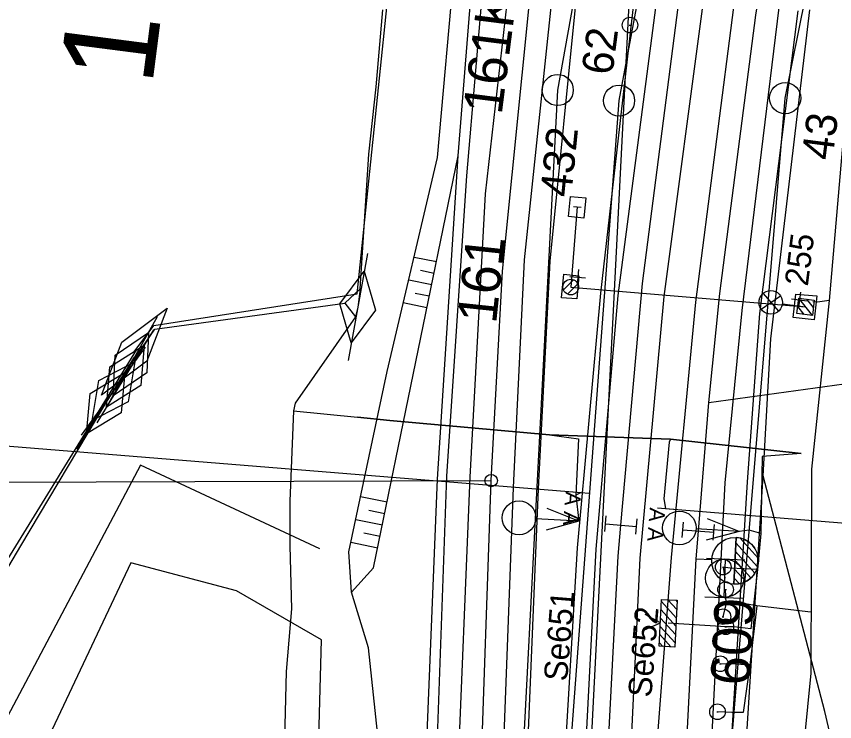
# Model space of a CAD drawing. Extents: x -598638 to -597933, y -1164002 to -1161904.
# Drawn here: x -598282.7 to -598230.2, y -1163124 to -1163078.8 of the extents above; entities that cross this region are included whole.
import ezdxf

# ---------------------------------------------------------------- set-up
doc = ezdxf.new("R2010")
doc.units = 0
for name, color, linetype in [('Vrstva 1', 7, 'Continuous'), ('Vrstva 11', 7, 'Continuous'), ('Vrstva 12', 7, 'Continuous'), ('Vrstva 2', 7, 'Continuous'), ('Vrstva 25', 7, 'Continuous'), ('Vrstva 26', 7, 'Continuous'), ('Vrstva 28', 7, 'Continuous'), ('Vrstva 3', 7, 'Continuous'), ('Vrstva 35', 7, 'Continuous'), ('Vrstva 36', 7, 'Continuous'), ('Vrstva 4', 7, 'Continuous'), ('Vrstva 43', 7, 'Continuous'), ('Vrstva 44', 7, 'Continuous'), ('Vrstva 48', 7, 'Continuous'), ('Vrstva 49', 7, 'Continuous'), ('Vrstva 51', 7, 'Continuous'), ('Vrstva 6', 7, 'Continuous'), ('Vrstva 63', 7, 'Continuous'), ('Vrstva 7', 7, 'Continuous')]:
    doc.layers.add(name, color=color, linetype=linetype)

msp = doc.modelspace()

# ---------------------------------------------------------------- linework, layer by layer
at = {"layer": 'Vrstva 1'}
for p, q in [((-598238.259, -1163103.539), (-598111.953, -1163086.041)), ((-598328.722, -1163108.807), (-598252.219, -1163108.544))]:
    msp.add_line(p, q, dxfattribs=at)
for points in [[(-598245.185, -1163146.686), (-598244.89, -1163128.996), (-598244.069, -1163113.383), (-598243.892, -1163111.402), (-598242.508, -1163095.903), (-598240.221, -1163078.173), (-598237.7, -1163063), (-598234.456, -1163047.036), (-598230.819, -1163031.867), (-598224.044, -1163008.196), (-598218.147, -1162990.962), (-598212.612, -1162976.381), (-598210.162, -1162970.38), (-598207.127, -1162963.269), (-598201.66, -1162951.286), (-598200.923, -1162949.67), (-598193.375, -1162934.568), (-598185.535, -1162920.228)], [(-598240.169, -1163146.755), (-598239.921, -1163130.309), (-598239.07, -1163113.566), (-598238.926, -1163111.785), (-598238.259, -1163103.539), (-598237.54, -1163096.536), (-598235.247, -1163078.679), (-598233.075, -1163065.413), (-598229.628, -1163048.216), (-598226.08, -1163033.339), (-598219.335, -1163009.739), (-598213.514, -1162992.625), (-598208.094, -1162978.373), (-598205.572, -1162972.188), (-598202.745, -1162965.549), (-598196.38, -1162951.607), (-598188.854, -1162936.558), (-598181.238, -1162922.581)], [(-598252.219, -1163108.544), (-598251.499, -1163095.121), (-598249.615, -1163076.345), (-598247.361, -1163061.217), (-598244.383, -1163046.003), (-598242.664, -1163039.018), (-598240.128, -1163028.714), (-598235.674, -1163014.439), (-598232.556, -1163004.447), (-598225.931, -1162987.141), (-598216.898, -1162967.125), (-598213.283, -1162959.931), (-598210.092, -1162954.031), (-598206.72, -1162947.797)], [(-598254.941, -1163186.204), (-598253.423, -1163142.963), (-598252.923, -1163128.846), (-598252.219, -1163108.544)]]:
    msp.add_lwpolyline(points, dxfattribs=at)
msp.add_circle((-598252.219, -1163108.544), 0.4, dxfattribs=at)
at = {"layer": 'Vrstva 11'}
for p, q in [((-598247.571, -1163096.314), (-598246.925, -1163095.668)), ((-598247.311, -1163096.584), (-598246.656, -1163095.929)), ((-598231.616, -1163097.956), (-598232.487, -1163096.847)), ((-598231.55, -1163097.433), (-598231.964, -1163096.907)), ((-598232.142, -1163097.893), (-598232.55, -1163097.373))]:
    msp.add_line(p, q, dxfattribs=at)
for points in [[(-598247.11, -1163096.13), (-598232.05, -1163097.4)], [(-598232.606, -1163097.837), (-598232.487, -1163096.844), (-598231.494, -1163096.963), (-598231.613, -1163097.956), (-598232.606, -1163097.837)]]:
    msp.add_lwpolyline(points, dxfattribs=at)
msp.add_lwpolyline([(-598232.606, -1163097.837), (-598232.487, -1163096.844), (-598231.494, -1163096.963), (-598231.613, -1163097.956)], close=True, dxfattribs=at)
msp.add_circle((-598247.11, -1163096.13), 0.5, dxfattribs=at)
at = {"layer": 'Vrstva 12'}
for points in [[(-598246.15, -1163090.4), (-598246.28, -1163091.71), (-598247.26, -1163091.61), (-598247.13, -1163090.33), (-598246.15, -1163090.4)], [(-598246.6, -1163095.4), (-598246.72, -1163096.89), (-598247.71, -1163096.82), (-598247.55, -1163095.31), (-598246.6, -1163095.4)], [(-598232.85, -1163098.08), (-598232.67, -1163096.58), (-598231.32, -1163096.7), (-598231.5, -1163098.23), (-598232.85, -1163098.08)]]:
    msp.add_lwpolyline(points, dxfattribs=at)
at = {"layer": 'Vrstva 2'}
for p, q in [((-598236.497, -1163112.195), (-598236.649, -1163115.191)), ((-598236.649, -1163115.191), (-598236.497, -1163112.195)), ((-598235.126, -1163114.074), (-598236.514, -1163112.537)), ((-598235.085, -1163113.523), (-598236.252, -1163112.231)), ((-598235.299, -1163114.479), (-598236.543, -1163113.102)), ((-598239.07, -1163113.566), (-598238.071, -1163113.617)), ((-598235.557, -1163114.791), (-598236.572, -1163113.667)), ((-598235.887, -1163115.022), (-598236.601, -1163114.232)), ((-598236.299, -1163115.164), (-598236.629, -1163114.796))]:
    msp.add_line(p, q, dxfattribs=at)
msp.add_lwpolyline([(-598240.169, -1163146.755), (-598239.921, -1163130.309), (-598239.07, -1163113.566)], dxfattribs=at)
msp.add_circle((-598236.573, -1163113.693), 1.5, dxfattribs=at)
msp.add_arc((-598236.573, -1163113.693), 1.5, 267.0903, 87.0903, dxfattribs=at)
at = {"layer": 'Vrstva 25'}
for p, q in [((-598234.909, -1163097.538), (-598233.666, -1163096.685)), ((-598234.766, -1163096.533), (-598233.795, -1163097.687)), ((-598233.538, -1163097.212), (-598232.05, -1163097.4)), ((-598237.38, -1163114.09), (-598237.28, -1163114.09)), ((-598237.233, -1163115.538), (-598237.133, -1163115.538)), ((-598237.402, -1163117.276), (-598237.302, -1163117.276)), ((-598237.22, -1163117.92), (-598237.12, -1163117.92)), ((-598237.57, -1163120.295), (-598237.47, -1163120.295)), ((-598237.75, -1163123.375), (-598237.65, -1163123.375))]:
    msp.add_line(p, q, dxfattribs=at)
for centre, radius in [((-598234.283, -1163097.113), 0.754), ((-598237.329, -1163114.09), 0.5), ((-598237.183, -1163115.538), 0.5), ((-598237.352, -1163117.276), 0.5), ((-598237.164, -1163117.92), 0.5), ((-598237.52, -1163120.295), 0.5), ((-598237.7, -1163123.375), 0.5)]:
    msp.add_circle(centre, radius, dxfattribs=at)
at = {"layer": 'Vrstva 26'}
for points in [[(-598211.382, -1162940.065), (-598193.601, -1162950.161), (-598191.584, -1162951.092), (-598198.026, -1162967.205), (-598208.688, -1162993.504), (-598209.03, -1162994.474), (-598214.707, -1163009.33), (-598218.558, -1163024.082), (-598220.34, -1163031.684), (-598220.756, -1163034.417), (-598224.218, -1163049.876), (-598227.646, -1163065.71), (-598228.067, -1163068.213), (-598230.531, -1163097), (-598231.676, -1163107.807), (-598231.723, -1163120.907), (-598232.574, -1163129.537), (-598231.426, -1163150.759)], [(-598275.109, -1163100.278), (-598273.844, -1163098.6), (-598260.82, -1163096.56), (-598257.46, -1163064.133), (-598260.892, -1163061.98), (-598261.588, -1163060.825), (-598273.046, -1163054.115), (-598278.317, -1163050.938), (-598277.838, -1163049.549), (-598266.333, -1163029.926), (-598256.715, -1163013.724), (-598243.958, -1162995.4), (-598237.708, -1162985.218), (-598234.448, -1162986.452), (-598224.79, -1162970.405), (-598223.9, -1162969.714), (-598230.146, -1162966.324)], [(-598230.531, -1163097), (-598231.278, -1163097.099), (-598231.586, -1163097.079)], [(-598277.216, -1163103.073), (-598275.908, -1163099.676), (-598273.002, -1163097.483), (-598274.31, -1163100.88), (-598277.216, -1163103.073)], [(-598329.728, -1163196.743), (-598319.392, -1163178.856), (-598305.552, -1163153.711), (-598290.936, -1163126.707), (-598284.955, -1163116.365), (-598274.949, -1163100.139)], [(-598231.709, -1163116.985), (-598235.178, -1163116.569), (-598236.052, -1163116.428), (-598237.149, -1163116.405), (-598237.183, -1163115.538)], [(-598235.178, -1163116.569), (-598235.634, -1163120.375), (-598236.055, -1163123.43), (-598236.789, -1163123.42), (-598237.7, -1163123.375)], [(-598237.149, -1163116.405), (-598237.352, -1163117.276)], [(-598235.634, -1163120.375), (-598236.512, -1163120.331), (-598237.52, -1163120.295)]]:
    msp.add_lwpolyline(points, dxfattribs=at)
at = {"layer": 'Vrstva 28'}
for p, q in [((-598260.148, -1163093.975), (-598261.393, -1163100.845)), ((-598261.916, -1163097.203), (-598260.355, -1163095.121)), ((-598260.355, -1163095.121), (-598259.625, -1163097.618)), ((-598261.186, -1163099.7), (-598261.916, -1163097.203)), ((-598259.625, -1163097.618), (-598261.186, -1163099.7)), ((-598277.026, -1163104.116), (-598273.614, -1163098.024)), ((-598277.482, -1163104.834), (-598273.858, -1163098.866)), ((-598276.336, -1163100.502), (-598274.183, -1163099.04)), ((-598274.183, -1163099.04), (-598274.304, -1163101.639)), ((-598278.48, -1163105.636), (-598274.381, -1163099.984)), ((-598276.665, -1163101.246), (-598274.463, -1163099.861)), ((-598274.463, -1163099.861), (-598274.675, -1163102.454)), ((-598278.796, -1163106.537), (-598275.085, -1163100.624)), ((-598276.457, -1163103.101), (-598276.336, -1163100.502)), ((-598277.373, -1163102.127), (-598275.064, -1163100.926)), ((-598275.064, -1163100.926), (-598275.488, -1163103.493)), ((-598277.926, -1163102.962), (-598275.703, -1163101.609)), ((-598276.878, -1163103.839), (-598276.665, -1163101.246)), ((-598274.304, -1163101.639), (-598276.457, -1163103.101)), ((-598275.703, -1163101.609), (-598275.954, -1163104.199)), ((-598277.796, -1163104.694), (-598277.373, -1163102.127)), ((-598274.675, -1163102.454), (-598276.878, -1163103.839)), ((-598278.177, -1163105.551), (-598277.926, -1163102.962)), ((-598275.488, -1163103.493), (-598277.796, -1163104.694)), ((-598275.954, -1163104.199), (-598278.177, -1163105.551)), ((-598240.343, -1163117.354), (-598241.294, -1163116.308)), ((-598240.318, -1163116.825), (-598240.888, -1163116.197)), ((-598240.292, -1163116.296), (-598240.358, -1163116.222)), ((-598240.369, -1163117.885), (-598241.319, -1163116.838)), ((-598240.394, -1163118.414), (-598241.345, -1163117.367)), ((-598240.42, -1163118.943), (-598241.371, -1163117.897)), ((-598240.685, -1163119.21), (-598241.396, -1163118.427)), ((-598241.214, -1163119.184), (-598241.422, -1163118.956))]:
    msp.add_line(p, q, dxfattribs=at)
for points in [[(-598260.62, -1163096.25), (-598260.07, -1163087.61), (-598259.59, -1163083.29), (-598259.16, -1163078.34)], [(-598261.6, -1163097.17), (-598260.62, -1163096.25), (-598260.77, -1163097.41), (-598260.92, -1163098.05)], [(-598311.69, -1163165.97), (-598300.22, -1163144.81), (-598288.63, -1163123.27), (-598282.38, -1163112.74), (-598276.94, -1163103.58), (-598276.43, -1163102.81), (-598275.67, -1163101.85), (-598275.32, -1163101.07), (-598273.79, -1163098.83), (-598261.6, -1163097.17), (-598260.92, -1163098.05), (-598264.78, -1163103.58), (-598264.9, -1163104.07), (-598265.13, -1163109.86), (-598265.13, -1163112.72), (-598265.03, -1163116.78), (-598265.37, -1163120.79), (-598265.62, -1163131.18), (-598265.34, -1163148.04), (-598265.46, -1163176.63)], [(-598264.9, -1163104.07), (-598260.79, -1163104.47), (-598258.71, -1163104.69), (-598248.47, -1163105.62), (-598240.71, -1163105.88), (-598232.34, -1163106.8), (-598234.84, -1163106.99), (-598234.93, -1163111.94), (-598235.14, -1163114.25), (-598235.56, -1163118.05), (-598236.65, -1163117.92), (-598237.17, -1163117.92), (-598240.86, -1163117.7)], [(-598248.47, -1163105.62), (-598246.62, -1163105.87), (-598246.78, -1163109.47), (-598246.59, -1163111.14)], [(-598240.71, -1163105.88), (-598240.79, -1163106.09), (-598241.15, -1163109.72), (-598241.04, -1163110.34)], [(-598246.44, -1163109.31), (-598246.78, -1163109.47)], [(-598234.93, -1163111.94), (-598235.67, -1163111.73), (-598236.31, -1163111.81)], [(-598235.14, -1163114.25), (-598236.88, -1163114.17), (-598237.33, -1163114.09), (-598237.23, -1163114.81)], [(-598241.433, -1163119.173), (-598241.287, -1163116.178), (-598240.288, -1163116.226), (-598240.433, -1163119.222), (-598241.433, -1163119.173)], [(-598242.382, -1163118.127), (-598241.359, -1163117.676), (-598242.334, -1163117.127)]]:
    msp.add_lwpolyline(points, dxfattribs=at)
msp.add_lwpolyline([(-598241.433, -1163119.173), (-598241.287, -1163116.178), (-598240.288, -1163116.226), (-598240.433, -1163119.222)], close=True, dxfattribs=at)
at = {"layer": 'Vrstva 3'}
for p, q in [((-598246.59, -1163111.14), (-598248.62, -1163110.341)), ((-598246.59, -1163111.14), (-598249.346, -1163110.993)), ((-598244.934, -1163111.808), (-598244.842, -1163110.812)), ((-598242.942, -1163111.992), (-598242.85, -1163110.996)), ((-598236.31, -1163111.81), (-598238.336, -1163110.999)), ((-598246.59, -1163111.14), (-598248.694, -1163111.719)), ((-598244.888, -1163111.31), (-598242.896, -1163111.494)), ((-598239.962, -1163112.204), (-598239.883, -1163111.207)), ((-598236.31, -1163111.81), (-598239.065, -1163111.647)), ((-598237.969, -1163112.363), (-598237.89, -1163111.366)), ((-598239.923, -1163111.706), (-598237.929, -1163111.864)), ((-598236.31, -1163111.81), (-598238.417, -1163112.377)), ((-598238.412, -1163113.53), (-598235.95, -1163113.628)), ((-598237.279, -1163116.041), (-598237.181, -1163113.579)), ((-598238.51, -1163115.992), (-598236.048, -1163116.09))]:
    msp.add_line(p, q, dxfattribs=at)
for centre, radius in [((-598250.428, -1163110.932), 1.084), ((-598240.146, -1163111.586), 1.084), ((-598237.234, -1163114.804), 1.232)]:
    msp.add_circle(centre, radius, dxfattribs=at)
at = {"layer": 'Vrstva 35'}
msp.add_lwpolyline([(-598232.34, -1163106.8), (-598240.71, -1163105.88), (-598248.47, -1163105.62), (-598258.71, -1163104.69), (-598260.79, -1163104.47)], dxfattribs=at)
at = {"layer": 'Vrstva 36'}
msp.add_line((-598246.942, -1163090.965), (-598246.444, -1163091.014), dxfattribs=at)
msp.add_lwpolyline([(-598246.69, -1163090.99), (-598247.11, -1163096.13)], dxfattribs=at)
at = {"layer": 'Vrstva 4'}
for points in [[(-598398.167, -1163553.239), (-598376.487, -1163515.918), (-598348.795, -1163467.979), (-598339.716, -1163452.202), (-598323.266, -1163423.236), (-598308.372, -1163396.471), (-598302.715, -1163384.123), (-598298.324, -1163372.137), (-598289.593, -1163344.221), (-598282.967, -1163321.229), (-598274.797, -1163290.285), (-598269.404, -1163272.781), (-598266.519, -1163258.633), (-598263.896, -1163241.651), (-598261.185, -1163218.05), (-598260.503, -1163217.001), (-598259.092, -1163201.513), (-598258.163, -1163186.176), (-598256.557, -1163141.317), (-598256.485, -1163129.008), (-598255.651, -1163108.451), (-598254.34, -1163087.718), (-598253.319, -1163075.132)], [(-598321.684, -1163563.952), (-598314.649, -1163552.341), (-598302.065, -1163529.781), (-598292.77, -1163512.02), (-598281.731, -1163489.572), (-598274.163, -1163472.668), (-598266.066, -1163452.17), (-598258.953, -1163431.709), (-598252.674, -1163410.241), (-598246.46, -1163386.104), (-598243.144, -1163368.884), (-598239.955, -1163345.756), (-598237.56, -1163323.253), (-598236.679, -1163305.47), (-598236.283, -1163282.744), (-598236.431, -1163244.569), (-598236.596, -1163214.625), (-598236.873, -1163174.881), (-598236.229, -1163131.239), (-598234.781, -1163108.249), (-598234.285, -1163099.455), (-598231.787, -1163078.342)], [(-598283.36, -1163489.15), (-598275.736, -1163471.917), (-598267.551, -1163451.028), (-598260.793, -1163431.262), (-598254.345, -1163409.722), (-598248.47, -1163385.636), (-598245.045, -1163368.352), (-598241.712, -1163345.6), (-598239.462, -1163322.753), (-598238.478, -1163305.467), (-598238.203, -1163283.28), (-598238.406, -1163245.16), (-598238.376, -1163215.168), (-598238.53, -1163175.26), (-598238.394, -1163131.328), (-598237.202, -1163108.683), (-598236.122, -1163097.625), (-598233.737, -1163078.205)]]:
    msp.add_lwpolyline(points, dxfattribs=at)
at = {"layer": 'Vrstva 43'}
for centre in [(-598247.948, -1163083.491), (-598244.014, -1163084.171), (-598233.358, -1163084.011)]:
    msp.add_circle(centre, 1, dxfattribs=at)
at = {"layer": 'Vrstva 44'}
for points in [[(-598295.758, -1163493.483), (-598278.118, -1163452.874), (-598264.209, -1163410.565), (-598254.468, -1163367.19), (-598248.62, -1163321.577), (-598253.497, -1163320.887), (-598249.615, -1163272.581), (-598247.635, -1163222.481), (-598247.486, -1163176.779), (-598247.442, -1163130.148), (-598244.014, -1163084.171), (-598235.33, -1163037.762), (-598224.817, -1163002.559), (-598219.379, -1163002.169), (-598206.652, -1162968.487), (-598191.401, -1162936.053), (-598173.754, -1162904.506), (-598155.689, -1162873.083), (-598136.14, -1162838.446), (-598116.776, -1162804.197)], [(-598286.823, -1163498.793), (-598268.977, -1163457.491), (-598254.684, -1163414.899), (-598244.494, -1163370.7), (-598238.629, -1163323.594), (-598237.183, -1163277.386), (-598237.387, -1163227.403), (-598237.546, -1163176.839), (-598237.218, -1163130.355), (-598233.358, -1163084.011), (-598224.142, -1163038.365), (-598215.269, -1163005.578), (-598224.817, -1163002.559)], [(-598280.199, -1163332.648), (-598271.397, -1163301.809), (-598265.446, -1163302.712), (-598259.208, -1163252.741), (-598251.788, -1163176.385), (-598250.383, -1163130.296), (-598247.948, -1163083.491), (-598241.007, -1163044.927)]]:
    msp.add_lwpolyline(points, dxfattribs=at)
at = {"layer": 'Vrstva 48'}
for p, q in [((-598257.161, -1163094.203), (-598255.73, -1163094.497)), ((-598256.752, -1163095.053), (-598255.88, -1163095.231)), ((-598257.506, -1163095.664), (-598256.031, -1163095.966)), ((-598257.08, -1163096.517), (-598256.182, -1163096.701)), ((-598257.851, -1163097.124), (-598256.332, -1163097.435)), ((-598260.595, -1163109.564), (-598258.89, -1163109.914)), ((-598260.067, -1163110.438), (-598259.041, -1163110.649)), ((-598260.906, -1163111.032), (-598259.192, -1163111.383)), ((-598260.374, -1163111.906), (-598259.342, -1163112.118)), ((-598261.217, -1163112.499), (-598259.493, -1163112.853))]:
    msp.add_line(p, q, dxfattribs=at)
at = {"layer": 'Vrstva 49'}
for points in [[(-598299.445, -1163361.058), (-598297.068, -1163359.059), (-598293.068, -1163343.621), (-598287.79, -1163320.649), (-598279.637, -1163288.312), (-598274.636, -1163271.434), (-598271.523, -1163257.595), (-598269.283, -1163241.904), (-598267.104, -1163218.072), (-598264.127, -1163206.783), (-598263.144, -1163204.971), (-598260.62, -1163202.843), (-598259.578, -1163186.018), (-598258.253, -1163141.176), (-598259.192, -1163127.718), (-598260.075, -1163119.279), (-598261.182, -1163115.692), (-598261.349, -1163113.122), (-598258.894, -1163101.538), (-598255.65, -1163087.809), (-598254.518, -1163075.132), (-598252.098, -1163061.479), (-598247.841, -1163044.835)], [(-598261.182, -1163115.692), (-598259.756, -1163114.136), (-598254.34, -1163087.718)], [(-598263.212, -1163112.925), (-598274.704, -1163107.546), (-598303.252, -1163161.452), (-598319.987, -1163201.454), (-598331.61, -1163221.279), (-598337.803, -1163227.955), (-598369.667, -1163281.996), (-598397.721, -1163336.904), (-598402.66, -1163348.84), (-598400.565, -1163353.737), (-598397.481, -1163355.879), (-598399.949, -1163362.495), (-598406.763, -1163364.325), (-598409.804, -1163366.381), (-598423.526, -1163399.322), (-598428.665, -1163409.066), (-598433.221, -1163423.229), (-598435.507, -1163449.626)], [(-598218.985, -1163327.148), (-598212.65, -1163283.715), (-598208.558, -1163248.195), (-598210.74, -1163214.935), (-598218.187, -1163174.338), (-598225.543, -1163145.969), (-598230.824, -1163123.355), (-598234.781, -1163108.249)], [(-598271.914, -1163217.222), (-598269.776, -1163209.288), (-598269.073, -1163206.337), (-598265.809, -1163203.939), (-598262.679, -1163201.583), (-598261.749, -1163188.913), (-598261.649, -1163166.383), (-598262.017, -1163142.76), (-598263.36, -1163128.202), (-598263.105, -1163118.751), (-598268.545, -1163115.616), (-598275.334, -1163113.816), (-598312.096, -1163191.704), (-598312.746, -1163196.691)]]:
    msp.add_lwpolyline(points, dxfattribs=at)
at = {"layer": 'Vrstva 51'}
for points in [[(-598243.76, -1163139.382), (-598243.393, -1163128.836), (-598242.662, -1163113.52), (-598241.121, -1163096.732), (-598238.542, -1163077.297), (-598236.364, -1163063.881), (-598233.006, -1163047.35), (-598229.452, -1163032.186), (-598222.566, -1163008.635), (-598216.788, -1162991.447), (-598211.314, -1162977.141), (-598198.954, -1162949.031), (-598191.954, -1162935.136), (-598181.215, -1162915.654), (-598172.367, -1162900.092), (-598146.639, -1162854.694), (-598125.435, -1162817.431), (-598123.403, -1162813.873), (-598093.874, -1162762.323), (-598071.494, -1162722.83), (-598058.726, -1162701.732), (-598043.403, -1162678.606), (-598026.165, -1162652.845)], [(-598397.431, -1163553.318), (-598375.745, -1163515.943), (-598348.098, -1163468.333), (-598322.38, -1163423.533), (-598307.542, -1163396.818), (-598301.86, -1163384.541), (-598297.285, -1163372.341), (-598293.283, -1163359.379), (-598288.845, -1163344.448), (-598282.25, -1163321.235), (-598273.825, -1163290.423), (-598265.756, -1163258.778), (-598260.545, -1163219.203), (-598259.744, -1163217.171), (-598258.57, -1163201.891), (-598257.659, -1163186.255), (-598256.038, -1163142.193), (-598255.793, -1163128.623), (-598255.065, -1163108.27), (-598253.781, -1163088.998), (-598252.62, -1163075.466)], [(-598396.078, -1163554.151), (-598374.443, -1163516.599), (-598347.031, -1163469.014), (-598321.218, -1163424.261), (-598306.253, -1163397.723), (-598300.608, -1163385.153), (-598295.814, -1163372.93), (-598291.849, -1163359.988), (-598287.46, -1163344.41), (-598281.154, -1163322.32), (-598272.412, -1163291.197), (-598264.229, -1163259.135), (-598258.972, -1163219.27), (-598257.327, -1163201.644), (-598256.369, -1163186.491), (-598254.79, -1163142.649), (-598254.397, -1163128.629), (-598253.571, -1163108.317), (-598252.585, -1163090.153), (-598250.983, -1163076.012)], [(-598384.985, -1163560.822), (-598363.176, -1163523.063), (-598335.955, -1163475.581), (-598310.179, -1163431.066), (-598295.149, -1163404.135), (-598288.465, -1163389.583), (-598283.96, -1163377.815), (-598279.772, -1163364.473), (-598275.196, -1163348.33), (-598271.933, -1163336.198), (-598269.31, -1163324.265), (-598265.084, -1163292.029), (-598261.053, -1163259.678), (-598256.104, -1163220.296), (-598254.426, -1163201.671), (-598253.667, -1163187.936), (-598252.018, -1163143.494), (-598251.534, -1163128.863), (-598250.791, -1163108.998), (-598250.069, -1163094.383), (-598248.218, -1163076.729)], [(-598305.922, -1163504.285), (-598297.335, -1163487.137), (-598287.92, -1163465.981), (-598279.035, -1163443.103), (-598273.208, -1163425.978), (-598267.2, -1163406.108), (-598261.011, -1163380.887), (-598258.166, -1163366.304), (-598254.569, -1163343.143), (-598252.435, -1163322.084), (-598250.965, -1163305.051), (-598249.488, -1163286.133), (-598247.962, -1163266.793), (-598246.718, -1163245.404), (-598246.637, -1163214.417), (-598246.633, -1163173.748), (-598246.347, -1163129.422), (-598245.484, -1163112.939), (-598244.076, -1163096.672), (-598241.475, -1163076.865)], [(-598298.888, -1163486.593), (-598289.113, -1163465.583), (-598279.905, -1163442.964), (-598274.107, -1163425.699), (-598268.268, -1163405.757), (-598262.238, -1163380.596), (-598259.701, -1163366.461), (-598255.999, -1163342.847), (-598253.859, -1163322.319), (-598252.407, -1163304.609), (-598250.982, -1163286.31), (-598249.458, -1163266.6), (-598248.128, -1163245.447), (-598247.963, -1163214.31), (-598248.01, -1163173.778), (-598247.475, -1163130.652), (-598247.596, -1163128.349), (-598246.685, -1163112.866), (-598245.177, -1163096.514), (-598242.921, -1163076.624)], [(-598389.422, -1163572.47), (-598383.242, -1163561.018), (-598361.933, -1163523.985), (-598335.337, -1163477.363), (-598309.065, -1163431.797), (-598293.626, -1163404.644), (-598286.924, -1163390.082), (-598282.523, -1163378.361), (-598278.252, -1163364.663), (-598273.758, -1163348.557), (-598270.372, -1163336.656), (-598267.892, -1163324.623), (-598263.657, -1163291.858), (-598259.724, -1163259.57), (-598255.007, -1163220.516), (-598252.865, -1163201.196), (-598252.034, -1163187.935), (-598250.643, -1163143.798), (-598250.023, -1163129.244), (-598249.184, -1163109.078), (-598248.423, -1163094.475), (-598246.693, -1163077.089)], [(-598243.76, -1163139.382), (-598242.782, -1163139.432), (-598241.873, -1163129.303), (-598240.653, -1163113.474), (-598239.095, -1163097.092), (-598236.576, -1163077.501)], [(-598282.309, -1163489.477), (-598274.667, -1163472.413), (-598266.77, -1163451.853), (-598259.621, -1163431.675), (-598253.513, -1163410.04), (-598247.112, -1163385.98), (-598243.846, -1163368.944), (-598240.561, -1163345.639), (-598238.081, -1163322.667), (-598237.343, -1163305.453), (-598236.795, -1163282.909), (-598237.051, -1163244.829), (-598237.298, -1163214.833), (-598237.439, -1163175.203), (-598237.167, -1163131.222), (-598235.767, -1163108.629), (-598234.985, -1163097.818), (-598232.528, -1163078.41)]]:
    msp.add_lwpolyline(points, dxfattribs=at)
at = {"layer": 'Vrstva 6'}
for p, q in [((-598303.072, -1163104.716), (-598246.44, -1163109.31)), ((-598246.938, -1163109.27), (-598245.942, -1163109.35)), ((-598241.538, -1163110.3), (-598240.542, -1163110.38)), ((-598241.04, -1163110.34), (-598196.151, -1163113.981))]:
    msp.add_line(p, q, dxfattribs=at)
at = {"layer": 'Vrstva 63'}
msp.add_line((-598248.331, -1163175.227), (-598242.563, -1163062.027), dxfattribs=at)
at = {"layer": 'Vrstva 7'}
for p, q in [((-598243.362, -1163079.325), (-598243.262, -1163079.325)), ((-598246.623, -1163095.003), (-598246.711, -1163095.999)), ((-598247.165, -1163095.457), (-598246.169, -1163095.545)), ((-598232.944, -1163096.892), (-598231.952, -1163097.016)), ((-598232.386, -1163096.458), (-598232.51, -1163097.45))]:
    msp.add_line(p, q, dxfattribs=at)
msp.add_circle((-598243.312, -1163079.325), 0.5, dxfattribs=at)

# ---------------------------------------------------------------- texts
at = {"layer": 'Vrstva 11'}
for s, rotation, p in [('161K', 82.7658, (-598251.544, -1163085.124)), ('161', 83.9769, (-598251.901, -1163098.527))]:
    msp.add_text(s, height=2.5, rotation=rotation, dxfattribs=at).set_placement(p)
at = {"layer": 'Vrstva 2'}
msp.add_text('609', height=2.5, rotation=267.0903, dxfattribs=at).set_placement((-598237.868, -1163116.006))
at = {"layer": 'Vrstva 25'}
msp.add_text('255', height=1.5, rotation=82.7858, dxfattribs=at).set_placement((-598231.909, -1163096.115))
at = {"layer": 'Vrstva 43'}
for s, rotation, p in [('62', 82.65, (-598244.446, -1163082.585)), ('43', 82.6827, (-598230.332, -1163088.047)), ('432', 84.2701, (-598247.084, -1163090.41))]:
    msp.add_text(s, height=2, rotation=rotation, dxfattribs=at).set_placement(p)
at = {"layer": 'Vrstva 6'}
for s, height, rotation, p in [('A A', 1, 265.3624, (-598247.437, -1163109.229)), ('A A', 1, 265.3624, (-598242.037, -1163110.259)), ('Se651', 1.5, 85.3624, (-598247.345, -1163121.452)), ('Se652', 1.5, 85.3624, (-598241.945, -1163122.482))]:
    msp.add_text(s, height=height, rotation=rotation, dxfattribs=at).set_placement(p)
at = {"layer": 'Vrstva 7'}
msp.add_text('11,8', height=6, rotation=82.65, dxfattribs=at).set_placement((-598273.964, -1163083.276))

doc.saveas('drawing.dxf')
